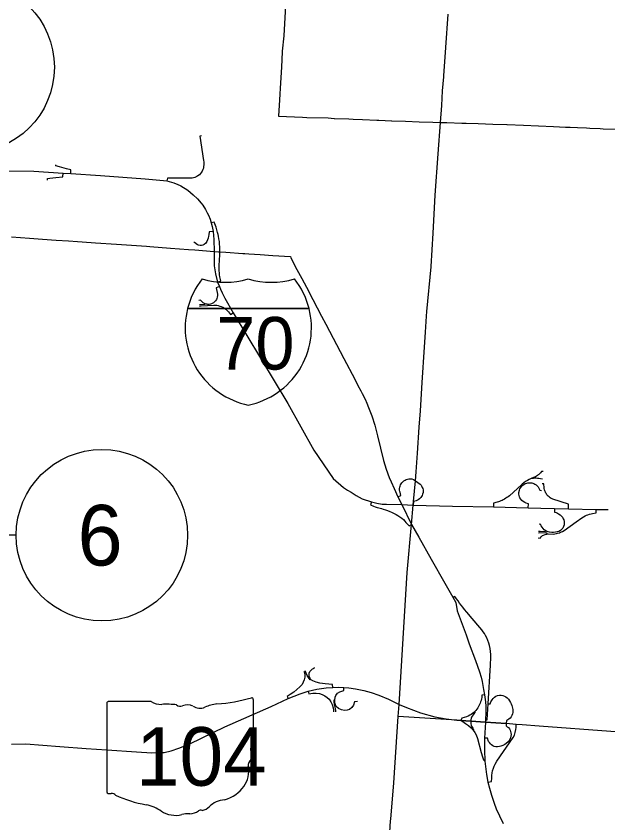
# Model space of a CAD drawing. Extents: x -1146 to -445, y -1283 to -822.
# Drawn here: x -856.5 to -821.35, y -1104.58 to -1056.63 of the extents above; entities that cross this region are included whole.
import ezdxf

# ---------------------------------------------------------------- set-up
doc = ezdxf.new("R2010")
doc.units = 0
for name, color, linetype in [('Default', 7, 'Continuous'), ('GM_X_Interchange_Ramps', 7, 'Continuous'), ('GM_X_Interstate_Route', 7, 'Continuous'), ('GM_X_Interstate_Shield', 7, 'Continuous'), ('GM_X_State_Route', 7, 'Continuous'), ('GM_X_State_Shield', 7, 'Continuous'), ('GM_X_Township', 7, 'Continuous'), ('GM_X_US_Route', 7, 'Continuous')]:
    doc.layers.add(name, color=color, linetype=linetype)

msp = doc.modelspace()

# ---------------------------------------------------------------- linework, layer by layer
at = {"layer": 'Default'}
msp.add_lwpolyline([(-856.505, -1087.481), (-859.052, -1087.481), (-858.201, -1065.733)], dxfattribs=at)
for centre in [(-859.326, -1059.664), (-851.41, -1087.481)]:
    msp.add_circle(centre, 5.094, dxfattribs=at)
at = {"layer": 'GM_X_Interchange_Ramps'}
for points in [[(-845.497, -1063.744), (-845.587, -1063.768), (-845.366, -1065.207), (-845.359, -1065.277), (-845.355, -1065.361), (-845.358, -1065.463), (-845.365, -1065.566), (-845.384, -1065.659), (-845.414, -1065.752), (-845.458, -1065.845), (-845.497, -1065.909), (-845.557, -1065.986), (-845.621, -1066.05), (-845.701, -1066.114), (-845.779, -1066.162), (-845.882, -1066.215), (-845.973, -1066.24), (-846.056, -1066.254), (-847.114, -1066.255), (-847.521, -1066.255), (-847.546, -1066.422)], [(-853.262, -1065.982), (-853.251, -1065.766), (-853.509, -1065.696), (-853.929, -1065.578), (-854.148, -1065.516), (-854.146, -1065.461)], [(-854.651, -1066.373), (-854.647, -1066.287), (-854.494, -1066.256), (-854.139, -1066.217), (-853.728, -1066.182), (-853.717, -1065.957)], [(-844.398, -1070.643), (-844.4, -1070.483), (-844.405, -1070.33), (-844.415, -1070.177), (-844.431, -1070.028), (-844.454, -1069.867), (-844.482, -1069.712), (-844.506, -1069.597), (-844.533, -1069.488), (-844.576, -1069.332), (-844.631, -1069.16), (-844.741, -1068.864), (-844.919, -1068.906)], [(-844.8, -1069.428), (-845.034, -1069.446), (-845.053, -1069.618), (-845.069, -1069.71), (-845.098, -1069.829), (-845.129, -1069.923), (-845.173, -1070.028), (-845.233, -1070.121), (-845.335, -1070.203), (-845.408, -1070.235), (-845.488, -1070.253), (-845.576, -1070.254), (-845.672, -1070.234), (-845.727, -1070.211), (-845.908, -1070.085), (-845.948, -1070.087)], [(-844.541, -1072.434), (-844.352, -1072.367), (-844.397, -1072.122), (-844.415, -1072), (-844.427, -1071.884), (-844.435, -1071.768), (-844.439, -1071.644), (-844.439, -1071.542), (-844.435, -1071.441), (-844.408, -1070.814), (-844.404, -1070.733), (-844.402, -1070.689), (-844.398, -1070.643)], [(-844.427, -1072.704), (-844.62, -1072.772), (-844.552, -1073.155), (-844.548, -1073.235), (-844.56, -1073.332), (-844.583, -1073.413), (-844.611, -1073.473), (-844.659, -1073.548), (-844.716, -1073.612), (-844.78, -1073.664), (-844.85, -1073.705), (-844.905, -1073.728), (-844.965, -1073.746), (-845.039, -1073.758), (-845.107, -1073.76), (-845.156, -1073.755), (-845.236, -1073.739), (-845.272, -1073.726), (-845.305, -1073.714), (-845.385, -1073.67), (-845.435, -1073.632), (-845.558, -1073.514), (-845.646, -1073.526)], [(-845.272, -1073.726), (-845.288, -1073.769), (-845.526, -1073.778), (-845.615, -1073.79)], [(-845.607, -1073.859), (-845.507, -1073.845), (-844.763, -1073.802), (-844.682, -1073.805), (-844.588, -1073.816), (-844.496, -1073.834), (-844.411, -1073.857), (-844.333, -1073.886), (-844.23, -1073.933), (-844.135, -1073.989), (-844.057, -1074.045), (-843.967, -1074.122), (-843.891, -1074.203), (-843.767, -1074.351), (-843.619, -1074.261)], [(-825.186, -1083.699), (-825.301, -1083.687), (-825.36, -1083.769), (-825.402, -1083.819), (-825.449, -1083.866), (-825.487, -1083.9), (-825.537, -1083.938), (-825.595, -1083.975), (-825.649, -1084.005), (-825.715, -1084.033), (-825.771, -1084.053), (-825.863, -1084.086), (-825.943, -1084.123), (-826.025, -1084.163), (-826.13, -1084.222), (-826.238, -1084.29), (-826.338, -1084.36), (-826.436, -1084.438), (-826.486, -1084.48), (-827.202, -1085.139), (-827.278, -1085.19), (-827.349, -1085.242), (-827.412, -1085.285), (-827.485, -1085.329), (-827.572, -1085.376), (-827.639, -1085.408), (-827.706, -1085.436), (-827.789, -1085.467), (-827.847, -1085.486), (-827.928, -1085.509), (-828.145, -1085.584), (-828.151, -1085.794)], [(-833.825, -1085.198), (-833.651, -1085.119), (-833.7, -1084.929), (-833.713, -1084.874), (-833.723, -1084.803), (-833.725, -1084.751), (-833.722, -1084.695), (-833.712, -1084.627), (-833.695, -1084.564), (-833.668, -1084.493), (-833.637, -1084.435), (-833.597, -1084.375), (-833.542, -1084.312), (-833.475, -1084.254), (-833.397, -1084.204), (-833.336, -1084.175), (-833.262, -1084.151), (-833.18, -1084.135), (-833.092, -1084.13), (-832.995, -1084.138), (-832.897, -1084.164), (-832.788, -1084.248), (-832.51, -1084.444), (-832.452, -1084.508), (-832.419, -1084.554), (-832.375, -1084.638), (-832.353, -1084.699), (-832.333, -1084.792), (-832.328, -1084.865), (-832.334, -1084.95), (-832.356, -1085.047), (-832.386, -1085.123), (-832.417, -1085.179), (-832.46, -1085.239), (-832.497, -1085.28), (-832.542, -1085.321), (-832.614, -1085.372), (-832.667, -1085.4), (-832.747, -1085.43), (-832.895, -1085.484), (-832.92, -1085.699)], [(-825.226, -1084.15), (-825.349, -1084.138), (-825.448, -1084.114), (-825.53, -1084.1), (-825.605, -1084.094), (-825.669, -1084.093), (-825.727, -1084.094), (-825.795, -1084.101), (-825.853, -1084.109), (-825.863, -1084.086)], [(-826.077, -1085.852), (-826.072, -1085.617), (-826.208, -1085.567), (-826.288, -1085.53), (-826.389, -1085.471), (-826.468, -1085.408), (-826.527, -1085.334), (-826.572, -1085.257), (-826.599, -1085.192), (-826.62, -1085.115), (-826.631, -1085.044), (-826.631, -1084.933), (-826.606, -1084.807), (-826.572, -1084.719), (-826.526, -1084.639), (-826.483, -1084.584), (-826.406, -1084.507), (-826.339, -1084.457), (-826.258, -1084.412), (-826.167, -1084.379), (-826.102, -1084.365), (-826.042, -1084.358), (-825.965, -1084.357), (-825.861, -1084.372), (-825.759, -1084.405), (-825.684, -1084.443), (-825.613, -1084.492), (-825.54, -1084.56), (-825.497, -1084.613), (-825.455, -1084.68), (-825.392, -1084.812), (-825.285, -1084.823)], [(-823.692, -1085.918), (-823.685, -1085.634), (-824.617, -1085.345), (-824.66, -1085.319), (-824.717, -1085.296), (-824.786, -1085.251), (-824.845, -1085.205), (-824.891, -1085.163), (-824.933, -1085.119), (-824.969, -1085.074), (-825, -1085.03), (-825.034, -1084.976), (-825.061, -1084.923), (-825.093, -1084.846), (-825.115, -1084.777), (-825.13, -1084.709), (-825.137, -1084.661), (-825.157, -1084.433), (-825.25, -1084.424)], [(-835.403, -1085.494), (-835.451, -1085.683), (-835.278, -1085.748), (-835.169, -1085.79), (-835.06, -1085.827), (-834.96, -1085.856), (-834.809, -1085.894), (-834.697, -1085.924), (-834.566, -1085.965), (-834.445, -1086.008), (-834.313, -1086.061), (-834.215, -1086.105), (-834.093, -1086.164), (-833.934, -1086.251), (-833.825, -1086.316), (-833.707, -1086.393), (-833.601, -1086.468), (-833.499, -1086.555), (-833.411, -1086.645), (-833.349, -1086.72), (-833.148, -1086.914), (-833.011, -1086.835)], [(-825.498, -1087.64), (-825.376, -1087.652), (-825.318, -1087.584), (-825.227, -1087.506), (-825.177, -1087.476), (-825.078, -1087.433), (-825.01, -1087.416), (-824.974, -1087.412), (-824.898, -1087.405), (-824.609, -1087.415), (-824.504, -1087.402), (-824.41, -1087.384), (-824.341, -1087.367), (-824.231, -1087.332), (-824.156, -1087.302), (-824.054, -1087.255), (-823.952, -1087.197), (-823.243, -1086.686), (-822.896, -1086.454), (-822.797, -1086.39), (-822.697, -1086.335), (-822.616, -1086.296), (-822.536, -1086.264), (-822.442, -1086.232), (-822.35, -1086.206), (-822.267, -1086.188), (-822.052, -1086.155), (-822.051, -1085.953)], [(-824.513, -1085.895), (-824.518, -1086.11), (-824.423, -1086.139), (-824.351, -1086.17), (-824.275, -1086.212), (-824.19, -1086.273), (-824.109, -1086.35), (-824.056, -1086.412), (-823.999, -1086.499), (-823.964, -1086.569), (-823.944, -1086.665), (-823.942, -1086.788), (-823.956, -1086.87), (-823.988, -1086.965), (-824.036, -1087.052), (-824.093, -1087.124), (-824.171, -1087.193), (-824.273, -1087.253), (-824.369, -1087.285), (-824.462, -1087.303), (-824.575, -1087.313), (-824.69, -1087.311), (-824.814, -1087.295), (-824.951, -1087.259), (-825.032, -1087.227), (-825.132, -1087.156), (-825.198, -1087.087), (-825.264, -1086.999), (-825.305, -1086.926), (-825.343, -1086.839), (-825.426, -1086.831)], [(-825.472, -1087.334), (-825.39, -1087.328), (-824.98, -1087.346), (-824.974, -1087.412)], [(-825.032, -1087.227), (-825.053, -1087.28), (-825.381, -1087.265), (-825.467, -1087.256)], [(-828.613, -1098.448), (-828.525, -1098.451), (-828.471, -1097.503), (-828.332, -1095.213), (-828.302, -1094.719), (-828.303, -1094.566), (-828.316, -1094.385), (-828.341, -1094.217), (-828.381, -1094.035), (-828.42, -1093.898), (-828.474, -1093.747), (-828.549, -1093.576), (-828.62, -1093.438), (-828.688, -1093.324), (-828.754, -1093.225), (-828.848, -1093.1), (-829.531, -1092.285), (-829.618, -1092.188), (-829.727, -1092.061), (-829.86, -1091.902), (-829.971, -1091.763), (-830.063, -1091.643), (-830.162, -1091.51), (-830.25, -1091.388), (-830.334, -1091.267), (-830.437, -1091.114), (-830.558, -1091.172)], [(-839.411, -1095.58), (-839.392, -1095.608), (-839.354, -1095.783), (-839.354, -1095.921), (-839.386, -1096.07), (-839.445, -1096.208), (-839.519, -1096.352), (-839.647, -1096.496), (-839.822, -1096.65), (-840.013, -1096.804), (-840.226, -1096.948), (-840.401, -1097.059), (-840.346, -1097.192)], [(-839.009, -1096.06), (-839.035, -1096.08), (-839.093, -1096.003), (-839.143, -1095.929), (-839.213, -1095.816), (-839.28, -1095.688), (-839.322, -1095.584), (-839.335, -1095.536)], [(-837.692, -1096.523), (-837.712, -1096.363), (-838.143, -1096.31), (-838.462, -1096.272), (-838.69, -1096.224), (-838.876, -1096.145), (-839.009, -1096.06), (-839.066, -1095.94), (-839.091, -1095.854), (-839.095, -1095.773), (-839.091, -1095.679), (-839.058, -1095.588), (-839.026, -1095.539), (-838.987, -1095.497), (-838.904, -1095.432), (-838.786, -1095.384), (-838.792, -1095.341)], [(-836.23, -1097.37), (-836.399, -1097.383), (-836.463, -1097.586), (-836.564, -1097.724), (-836.697, -1097.835), (-836.835, -1097.883), (-837.005, -1097.894), (-837.175, -1097.867), (-837.351, -1097.782), (-837.489, -1097.665), (-837.558, -1097.511), (-837.579, -1097.394), (-837.579, -1097.277), (-837.553, -1097.112), (-837.51, -1097.001), (-837.409, -1096.878), (-837.282, -1096.783), (-837.165, -1096.74), (-837.037, -1096.708), (-837.038, -1096.528)], [(-839.151, -1096.75), (-839.11, -1096.905), (-838.876, -1096.868), (-838.679, -1096.868), (-838.483, -1096.889), (-838.329, -1096.942), (-838.164, -1097.027), (-838.02, -1097.123), (-837.909, -1097.235), (-837.808, -1097.378), (-837.728, -1097.548), (-837.664, -1097.74), (-837.643, -1097.899), (-837.642, -1097.979)], [(-828.675, -1096.973), (-828.831, -1096.988), (-828.844, -1097.118), (-828.863, -1097.207), (-828.886, -1097.306), (-828.911, -1097.389), (-828.941, -1097.469), (-828.99, -1097.579), (-829.034, -1097.663), (-829.08, -1097.736), (-829.141, -1097.822), (-829.201, -1097.896), (-829.263, -1097.963), (-829.322, -1098.019), (-829.391, -1098.078), (-829.475, -1098.141), (-829.544, -1098.186), (-829.643, -1098.231), (-829.744, -1098.269), (-830.022, -1098.348), (-830.09, -1098.498)], [(-828.471, -1097.503), (-828.341, -1097.511), (-828.305, -1097.38), (-828.224, -1097.256), (-828.162, -1097.179), (-828.084, -1097.109), (-827.999, -1097.056), (-827.9, -1097.016), (-827.796, -1096.995), (-827.696, -1096.991), (-827.582, -1097.008), (-827.496, -1097.037), (-827.414, -1097.078), (-827.331, -1097.139), (-827.257, -1097.217), (-827.19, -1097.315), (-827.132, -1097.42), (-827.09, -1097.512), (-827.058, -1097.598), (-827.033, -1097.678), (-827.006, -1097.831), (-827.006, -1098.012), (-827.02, -1098.102), (-827.051, -1098.196), (-827.099, -1098.282), (-827.162, -1098.359), (-827.225, -1098.414), (-827.302, -1098.463), (-827.381, -1098.497), (-827.392, -1098.678)], [(-837.516, -1097.987), (-837.515, -1097.899), (-837.538, -1097.796), (-837.559, -1097.677), (-837.583, -1097.538), (-837.605, -1097.388), (-837.611, -1097.273), (-837.579, -1097.277)], [(-829.263, -1097.963), (-829.232, -1097.994), (-829.276, -1098.041), (-829.324, -1098.103), (-829.356, -1098.153), (-829.405, -1098.228), (-829.444, -1098.301), (-829.466, -1098.357), (-829.486, -1098.453), (-829.49, -1098.532)], [(-829.49, -1098.532), (-829.495, -1098.614), (-829.483, -1098.688), (-829.465, -1098.762), (-829.443, -1098.829), (-829.417, -1098.89), (-829.383, -1098.955), (-829.353, -1099.005), (-829.323, -1099.047), (-829.344, -1099.062)], [(-827.392, -1098.678), (-827.398, -1098.804), (-827.324, -1098.86), (-827.262, -1098.916), (-827.205, -1098.986), (-827.16, -1099.063), (-827.129, -1099.144), (-827.11, -1099.232), (-827.106, -1099.33), (-827.13, -1099.521), (-827.172, -1099.618), (-827.213, -1099.681), (-827.28, -1099.758), (-827.393, -1099.856), (-827.479, -1099.912), (-827.601, -1099.976), (-827.704, -1100.017), (-827.781, -1100.041), (-827.916, -1100.062), (-828.005, -1100.055), (-828.103, -1100.031), (-828.181, -1099.998), (-828.266, -1099.944), (-828.333, -1099.883), (-828.391, -1099.81), (-828.436, -1099.732), (-828.503, -1099.544), (-828.677, -1099.542)], [(-828.476, -1102.159), (-828.255, -1102.119), (-828.253, -1101.911), (-828.248, -1101.753), (-828.224, -1101.602), (-828.201, -1101.483), (-828.151, -1101.332), (-828.111, -1101.211), (-828.052, -1101.084), (-827.953, -1100.914), (-826.969, -1099.497), (-826.904, -1099.359), (-826.852, -1099.201), (-826.812, -1099.03), (-826.799, -1098.904), (-826.797, -1098.82), (-826.797, -1098.722)]]:
    msp.add_lwpolyline(points, dxfattribs=at)
at = {"layer": 'GM_X_Interstate_Route'}
for points in [[(-869.676, -1064.867), (-869.502, -1064.876), (-868.343, -1064.938), (-867.698, -1064.958), (-867.022, -1065.071), (-865.683, -1065.265), (-864.06, -1065.444), (-863.075, -1065.58), (-861.315, -1065.675), (-860.131, -1065.719), (-859.67, -1065.737), (-859.312, -1065.748), (-856.96, -1065.825), (-855.462, -1065.843), (-853.717, -1065.957), (-853.262, -1065.982), (-851.494, -1066.091), (-848.831, -1066.296), (-847.742, -1066.389), (-847.546, -1066.422), (-847.131, -1066.539), (-846.894, -1066.633), (-846.756, -1066.698)], [(-846.756, -1066.698), (-846.72, -1066.715), (-846.306, -1066.976), (-845.992, -1067.241), (-845.731, -1067.477), (-845.511, -1067.737), (-845.416, -1067.869), (-845.263, -1068.112), (-845.162, -1068.311)], [(-845.162, -1068.311), (-845.078, -1068.461), (-844.976, -1068.702), (-844.919, -1068.906), (-844.866, -1069.133), (-844.8, -1069.428), (-844.763, -1069.912), (-844.75, -1070.612)], [(-844.75, -1070.612), (-844.741, -1070.932), (-844.737, -1071.47), (-844.662, -1071.944), (-844.541, -1072.434), (-844.427, -1072.704), (-844.359, -1072.862), (-844.263, -1073.07), (-844.107, -1073.396), (-843.619, -1074.261), (-840.369, -1079.646), (-838.812, -1082.427), (-837.669, -1084.105), (-837.05, -1084.649), (-836.825, -1084.795), (-836.596, -1084.916)], [(-836.596, -1084.916), (-836.308, -1085.126), (-835.939, -1085.319), (-835.403, -1085.494)], [(-835.403, -1085.494), (-835.077, -1085.579), (-834.752, -1085.627), (-834.51, -1085.636), (-833.598, -1085.65)], [(-833.598, -1085.65), (-832.92, -1085.699), (-830.58, -1085.762), (-828.151, -1085.794), (-826.077, -1085.852), (-825.342, -1085.872), (-824.513, -1085.895), (-823.692, -1085.918), (-822.051, -1085.953), (-821.335, -1085.959)]]:
    msp.add_lwpolyline(points, dxfattribs=at)
at = {"layer": 'GM_X_Interstate_Shield'}
for p, q in [((-846.318, -1073.999), (-839.104, -1073.999)), ((-839.104, -1073.999), (-846.318, -1073.999)), ((-839.104, -1073.999), (-846.318, -1073.999))]:
    msp.add_line(p, q, dxfattribs=at)
for centre, start, end in [((-841.774, -1075.148), 141.669, 165.8066), ((-844.081, -1067.758), 253.0091, 286.9909), ((-841.342, -1067.758), 253.0091, 286.9909), ((-843.649, -1075.148), 14.1934, 38.331), ((-841.774, -1075.148), 165.8066, 258.463), ((-843.649, -1075.148), 281.537, 14.1934)]:
    msp.add_arc(centre, 4.688, start, end, dxfattribs=at)
at = {"layer": 'GM_X_State_Route'}
for points in [[(-856.774, -1099.893), (-855.932, -1099.879), (-853.916, -1100.046), (-852.342, -1100.148), (-851.121, -1100.243), (-849.345, -1100.356), (-848.447, -1100.408), (-848.135, -1100.402), (-847.702, -1100.392), (-847.299, -1100.301), (-846.831, -1100.145), (-846.18, -1099.884), (-844.111, -1098.872), (-841.345, -1097.654), (-840.346, -1097.192), (-839.64, -1096.912), (-839.325, -1096.803), (-839.151, -1096.75), (-838.65, -1096.64), (-838.227, -1096.566), (-838.094, -1096.555)], [(-838.094, -1096.555), (-837.692, -1096.523), (-837.355, -1096.51), (-837.038, -1096.528), (-836.738, -1096.554), (-836.338, -1096.615), (-835.858, -1096.71), (-835.639, -1096.769), (-835.412, -1096.837), (-834.963, -1096.989), (-834.377, -1097.228), (-833.757, -1097.538), (-833.314, -1097.718), (-832.492, -1098.033), (-831.629, -1098.284), (-830.96, -1098.403), (-830.319, -1098.474), (-830.09, -1098.498), (-830.072, -1098.507)], [(-830.09, -1098.498), (-829.49, -1098.532), (-828.623, -1098.583), (-827.392, -1098.678)], [(-830.072, -1098.507), (-829.967, -1098.562), (-829.803, -1098.665), (-829.624, -1098.785), (-829.463, -1098.924), (-829.344, -1099.062), (-829.252, -1099.201), (-829.175, -1099.354), (-829.098, -1099.557), (-828.884, -1100.386), (-828.803, -1100.656), (-828.737, -1100.826), (-828.658, -1100.914)]]:
    msp.add_lwpolyline(points, dxfattribs=at)
at = {"layer": 'GM_X_State_Shield'}
for p, q in [((-851.114, -1097.459), (-851.114, -1102.742)), ((-848.48, -1097.368), (-851.029, -1097.368)), ((-842.413, -1100.001), (-842.413, -1097.237)), ((-842.414, -1100), (-842.413, -1100.001))]:
    msp.add_line(p, q, dxfattribs=at)
for centre, major_axis, start_param, end_param in [((-851.015, -1097.448), (0.101, 0), 1.712693, 3.28349), ((-847.874, -1096.755), (0.978, 0), 4.042523, 4.731795), ((-847.549, -1100.334), (3.51, 0), 1.404758, 1.657858), ((-846.753, -1097.421), (0.282, 0), 3.836095, 5.185415), ((-846.339, -1098.031), (0.586, 0), 0.950623, 2.079405), ((-844.336, -1098.982), (1.856, 0), 1.699011, 2.107814), ((-845.513, -1090.166), (9.227, 0), 4.814394, 5.042369), ((-842.51, -1097.226), (0.0969, 0), 6.141152, 7.989035), ((-845.582, -1097.194), (0.705, 0), 4.081561, 5.145723), ((-842.517, -1100.012), (0.104, 0), 5.05454, 6.418171), ((-842.436, -1100.204), (0.15, 0), 1.883978, 3.671073), ((-843.389, -1100.553), (0.9, 0), 5.934695, 6.695948), ((-842.066, -1101.158), (0.655, 0), 2.387724, 3.262537), ((-844.996, -1101.509), (2.308, 0), 5.101752, 6.440018), ((-851.014, -1102.754), (0.102, 0), 3.00124, 4.508301), ((-850.998, -1102.213), (0.776, 0), 4.665946, 4.897461), ((-850.839, -1103.047), (0.28, 0), 0.519207, 1.627899), ((-847.307, -1098.301), (6.663, 0), 4.195997, 4.488961), ((-844.023, -1104.226), (1.264, 0), 1.647645, 2.488434), ((-849.293, -1105.116), (2.085, 0), 0.823519, 1.323587), ((-845.54, -1103.981), (0.198, 0), 1.147584, 2.315152), ((-845.624, -1103.254), (0.746, 0), 4.937069, 5.64225), ((-847.038, -1103.073), (1.323, 0), 4.026481, 4.996735), ((-846.274, -1104.9), (1.087, 0), 1.495662, 1.94098), ((-846.177, -1103.469), (0.705, 0), 4.691044, 5.507374)]:
    msp.add_ellipse(centre, major_axis=major_axis, ratio=0.8, start_param=start_param, end_param=end_param, dxfattribs=at)
at = {"layer": 'GM_X_Township'}
for points in [[(-816.926, -1099.458), (-825.428, -1098.824), (-826.443, -1098.745), (-826.797, -1098.722), (-827.392, -1098.678), (-828.623, -1098.583), (-829.49, -1098.532), (-830.09, -1098.497), (-830.319, -1098.474), (-833.801, -1098.25), (-833.757, -1097.538), (-833.272, -1089.704), (-833.011, -1086.835), (-832.92, -1085.699), (-832.895, -1085.484), (-832.788, -1084.248), (-832.745, -1083.711), (-832.657, -1082.599), (-832.555, -1081.066), (-832.49, -1080.077), (-832.379, -1078.406), (-832.239, -1076.299), (-832.18, -1075.405), (-832.117, -1074.458), (-832.098, -1074.175), (-831.851, -1071.532), (-831.849, -1071.499), (-831.725, -1069.52), (-831.617, -1067.276), (-831.441, -1064.81), (-831.286, -1062.942), (-831.224, -1061.935), (-831.169, -1061.071), (-831.104, -1060.234), (-831.097, -1060.15), (-831.04, -1059.338), (-830.982, -1058.489), (-830.845, -1056.503)], [(-834.503, -1108.493), (-834.261, -1104.464), (-834.254, -1104.352), (-834.074, -1102.195), (-833.801, -1098.25)]]:
    msp.add_lwpolyline(points, dxfattribs=at)
at = {"layer": 'GM_X_US_Route'}
for points in [[(-840.353, -1053.649), (-840.353, -1053.653), (-840.434, -1054.946), (-840.437, -1054.988), (-840.522, -1056.368), (-840.609, -1057.775), (-840.611, -1057.807), (-840.692, -1058.713), (-840.694, -1058.754), (-840.748, -1059.66), (-840.803, -1060.594), (-840.804, -1060.616), (-840.822, -1060.906), (-840.844, -1061.266)], [(-840.844, -1061.266), (-840.864, -1061.597), (-840.924, -1062.58)], [(-840.924, -1062.58), (-839.502, -1062.632), (-839.232, -1062.642), (-837.965, -1062.662), (-837.616, -1062.701), (-837.593, -1062.702), (-836.739, -1062.738), (-836.478, -1062.75), (-835.919, -1062.774), (-835.074, -1062.81), (-834.95, -1062.815), (-834.197, -1062.847), (-834.185, -1062.848), (-833.375, -1062.874), (-832.561, -1062.9), (-831.741, -1062.927), (-831.329, -1062.94)], [(-831.329, -1062.94), (-831.286, -1062.942), (-830.943, -1062.953), (-830.91, -1062.954), (-830.027, -1062.983), (-829.772, -1062.991), (-829.052, -1063.014), (-828.192, -1063.042), (-827.359, -1063.069), (-827.33, -1063.071), (-826.373, -1063.111), (-825.464, -1063.15), (-824.572, -1063.188), (-823.859, -1063.22), (-823.59, -1063.232), (-823.155, -1063.252), (-822.63, -1063.275), (-822.425, -1063.285), (-821.806, -1063.313), (-821.636, -1063.32), (-820.911, -1063.349)], [(-856.78, -1069.746), (-855.72, -1069.824), (-854.939, -1069.88), (-854.121, -1069.939), (-853.388, -1069.987), (-852.856, -1070.024), (-852.592, -1070.046), (-851.784, -1070.096), (-850.537, -1070.187), (-848.769, -1070.309), (-848.556, -1070.324), (-847.343, -1070.415), (-846.259, -1070.498)], [(-846.259, -1070.498), (-845.898, -1070.526), (-844.75, -1070.612), (-844.486, -1070.635)], [(-844.486, -1070.635), (-844.398, -1070.643), (-844.042, -1070.665), (-843.044, -1070.734), (-842.914, -1070.743)], [(-842.914, -1070.743), (-842.69, -1070.758), (-842.011, -1070.803), (-841.263, -1070.851), (-840.215, -1070.921)], [(-840.215, -1070.921), (-840.184, -1070.993), (-839.829, -1071.685), (-839.542, -1072.215), (-839.264, -1072.732), (-838.875, -1073.473), (-838.358, -1074.455), (-838.103, -1074.937), (-837.033, -1076.973), (-836.384, -1078.208), (-836.198, -1078.574), (-836.035, -1078.892), (-835.952, -1079.052)], [(-835.952, -1079.052), (-835.856, -1079.238), (-835.733, -1079.494), (-835.72, -1079.523)], [(-835.72, -1079.523), (-835.667, -1079.641), (-835.563, -1079.887), (-835.37, -1080.382), (-835.204, -1080.944), (-835.028, -1081.58), (-834.674, -1083.036), (-834.527, -1083.553), (-834.345, -1084.049), (-834.235, -1084.315), (-834.048, -1084.703), (-833.825, -1085.198), (-833.598, -1085.65)], [(-833.598, -1085.65), (-833.011, -1086.835), (-832.795, -1087.218)], [(-832.795, -1087.218), (-832.579, -1087.601)], [(-832.579, -1087.601), (-831.847, -1088.899), (-831.033, -1090.328), (-830.558, -1091.172), (-830.389, -1091.485), (-830.303, -1091.965), (-829.773, -1093.401), (-829.584, -1093.939), (-829.206, -1094.934), (-828.983, -1095.592), (-828.877, -1095.922), (-828.82, -1096.166), (-828.735, -1096.648), (-828.675, -1096.973), (-828.628, -1097.379), (-828.605, -1097.649), (-828.608, -1098.017), (-828.613, -1098.448)], [(-828.613, -1098.448), (-828.623, -1098.583), (-828.677, -1099.542), (-828.679, -1100.232), (-828.658, -1100.914)], [(-828.658, -1100.914), (-828.56, -1101.708), (-828.476, -1102.159), (-828.385, -1102.524), (-828.262, -1102.928), (-828.099, -1103.41), (-827.979, -1103.753), (-827.794, -1104.163), (-827.57, -1104.623)]]:
    msp.add_lwpolyline(points, dxfattribs=at)

# ---------------------------------------------------------------- texts
at = {"layer": 'Default'}
msp.add_text('6', height=3.6, dxfattribs=at).set_placement((-852.856, -1089.281))
at = {"layer": 'GM_X_Interstate_Shield'}
msp.add_text('70', height=3.125, dxfattribs=at).set_placement((-844.618, -1077.632))
at = {"layer": 'GM_X_State_Shield'}
msp.add_text('104', height=3.4805, dxfattribs=at).set_placement((-849.385, -1102.37))

doc.saveas('drawing.dxf')
